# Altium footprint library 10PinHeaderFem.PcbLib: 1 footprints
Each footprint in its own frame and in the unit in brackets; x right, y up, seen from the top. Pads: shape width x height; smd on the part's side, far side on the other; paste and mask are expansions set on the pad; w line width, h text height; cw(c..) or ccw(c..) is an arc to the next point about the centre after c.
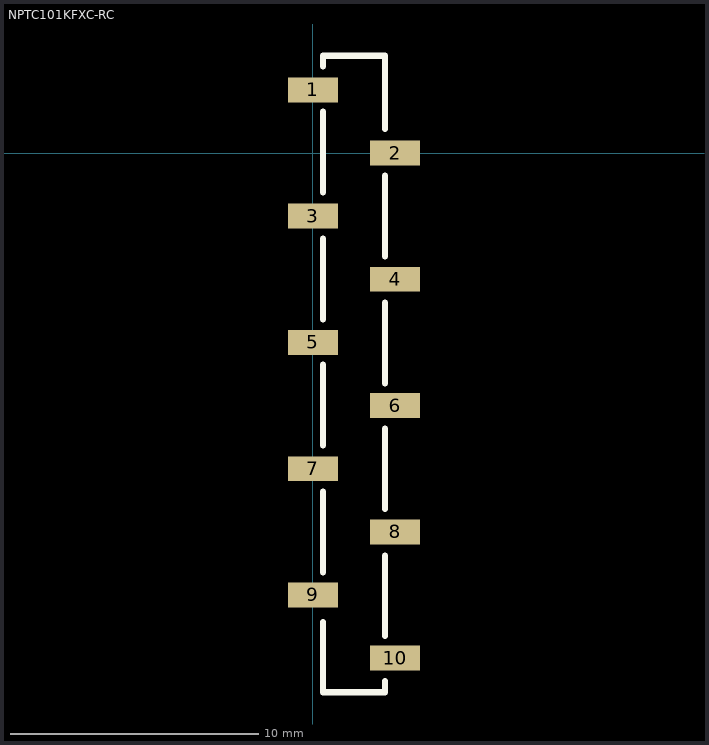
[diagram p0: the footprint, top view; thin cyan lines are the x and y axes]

## NPTC101KFXC-RC [mm] "Sullins Connector Solutions 10 pin female header. SMD."
height 0.4
pads (10):
  rect 2x1 smd: 1(0,2.54) 2(3.3,0) 3(0,-2.54) 4(3.3,-5.08) 5(0,-7.62) 6(3.3,-10.16) 7(0,-12.7) 8(3.3,-15.24) 9(0,-17.78) 10(3.3,-20.32)
Top Overlay:
  lines w0.254: 0.4,-18.88 0.4,-21.69 2.9,-21.69 2.9,-21.24 ; 0.4,-16.86 0.4,-13.62 ; 0.4,-11.75 0.4,-8.51 ; 0.4,-6.69 0.4,-3.45 ; 0.4,-1.58 0.4,1.66 ; 0.4,3.48 0.4,3.91 2.9,3.91 2.9,0.97 ; 2.9,-19.43 2.9,-16.19 ; 2.9,-14.32 2.9,-11.08 ; 2.9,-9.26 2.9,-6.02 ; 2.9,-4.15 2.9,-0.91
